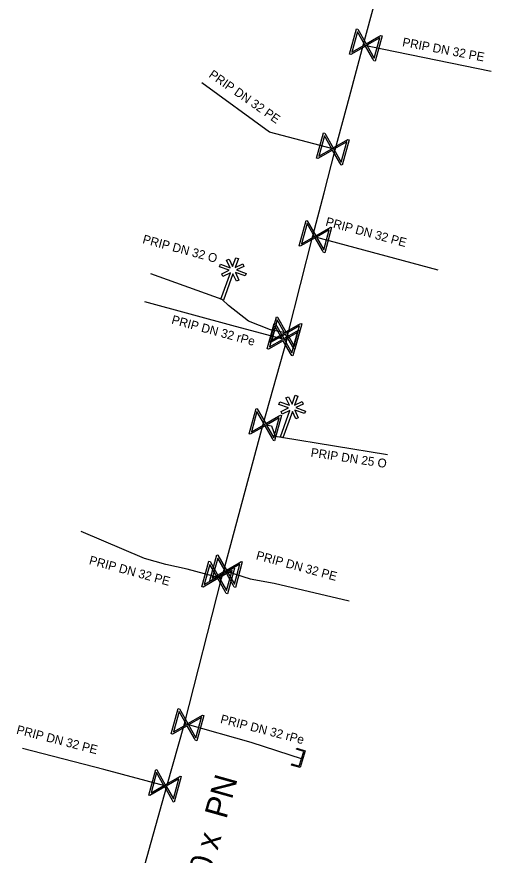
# Model space of a CAD drawing. Extents: x -643842 to -636370, y -1119190 to -1110210.
# Drawn here: x -641874.61 to -641847.68, y -1114927.07 to -1114879.49 of the extents above; entities that cross this region are included whole.
import ezdxf

# ---------------------------------------------------------------- set-up
doc = ezdxf.new("R2010")
doc.units = 0
for name, color, linetype in [('2', 7, 'Continuous'), ('22', 7, 'Continuous'), ('Level 16', 7, 'Continuous'), ('Level 20', 7, 'Continuous'), ('Level 21', 7, 'Continuous'), ('Level 23', 7, 'Continuous'), ('Level 4', 7, 'Continuous')]:
    doc.layers.add(name, color=color, linetype=linetype)

msp = doc.modelspace()

# ---------------------------------------------------------------- linework, layer by layer
at = {"layer": '2'}
for points in [[(-641862.359, -1114893.669), (-641862.177, -1114893.161), (-641862.03, -1114893.214), (-641862.21, -1114893.717), (-641861.787, -1114893.517), (-641861.721, -1114893.658), (-641862.141, -1114893.858), (-641861.599, -1114894.052), (-641861.652, -1114894.199), (-641862.203, -1114894.001), (-641862, -1114894.43), (-641862.141, -1114894.496), (-641862.339, -1114894.077), (-641862.874, -1114895.567), (-641863.021, -1114895.514), (-641862.485, -1114894.02), (-641862.912, -1114894.222), (-641862.977, -1114894.08), (-641862.549, -1114893.877), (-641863.1, -1114893.68), (-641863.047, -1114893.533), (-641862.506, -1114893.727), (-641862.703, -1114893.307), (-641862.562, -1114893.241), (-641862.359, -1114893.669)], [(-641858.989, -1114901.479), (-641858.807, -1114900.971), (-641858.66, -1114901.024), (-641858.84, -1114901.527), (-641858.417, -1114901.327), (-641858.351, -1114901.468), (-641858.771, -1114901.668), (-641858.229, -1114901.862), (-641858.282, -1114902.009), (-641858.833, -1114901.811), (-641858.63, -1114902.24), (-641858.771, -1114902.306), (-641858.969, -1114901.887), (-641859.504, -1114903.377), (-641859.651, -1114903.324), (-641859.115, -1114901.83), (-641859.542, -1114902.032), (-641859.607, -1114901.89), (-641859.179, -1114901.687), (-641859.73, -1114901.49), (-641859.677, -1114901.343), (-641859.136, -1114901.537), (-641859.333, -1114901.117), (-641859.192, -1114901.051), (-641858.989, -1114901.479)]]:
    msp.add_lwpolyline(points, dxfattribs=at)
at = {"layer": 'Level 16'}
for points in [[(-641853.878, -1114880.565), (-641854.274, -1114882.011), (-641854.337, -1114881.994), (-641854.397, -1114881.88), (-641854.814, -1114881.151), (-641855.657, -1114881.633), (-641855.72, -1114881.615), (-641855.324, -1114880.169), (-641855.261, -1114880.186), (-641854.781, -1114881.031), (-641854.052, -1114880.614), (-641853.941, -1114880.547), (-641853.878, -1114880.565)], [(-641855.59, -1114881.493), (-641854.858, -1114881.075), (-641855.275, -1114880.344), (-641855.59, -1114881.493)], [(-641854.01, -1114880.692), (-641854.738, -1114881.108), (-641854.322, -1114881.834), (-641854.01, -1114880.692)], [(-641855.749, -1114886.465), (-641856.145, -1114887.911), (-641856.208, -1114887.894), (-641856.268, -1114887.78), (-641856.685, -1114887.051), (-641857.528, -1114887.533), (-641857.591, -1114887.515), (-641857.195, -1114886.069), (-641857.132, -1114886.086), (-641856.652, -1114886.931), (-641855.923, -1114886.514), (-641855.812, -1114886.447), (-641855.749, -1114886.465)], [(-641857.461, -1114887.393), (-641856.729, -1114886.975), (-641857.146, -1114886.244), (-641857.461, -1114887.393)], [(-641855.881, -1114886.592), (-641856.609, -1114887.008), (-641856.193, -1114887.734), (-641855.881, -1114886.592)], [(-641856.739, -1114891.445), (-641857.135, -1114892.891), (-641857.198, -1114892.874), (-641857.258, -1114892.76), (-641857.675, -1114892.031), (-641858.518, -1114892.513), (-641858.581, -1114892.495), (-641858.185, -1114891.049), (-641858.122, -1114891.066), (-641857.642, -1114891.911), (-641856.913, -1114891.494), (-641856.802, -1114891.427), (-641856.739, -1114891.445)], [(-641858.451, -1114892.373), (-641857.719, -1114891.955), (-641858.136, -1114891.224), (-641858.451, -1114892.373)], [(-641856.871, -1114891.572), (-641857.599, -1114891.988), (-641857.183, -1114892.714), (-641856.871, -1114891.572)], [(-641858.429, -1114896.905), (-641858.825, -1114898.351), (-641858.888, -1114898.334), (-641858.948, -1114898.22), (-641859.365, -1114897.491), (-641860.208, -1114897.973), (-641860.271, -1114897.955), (-641859.875, -1114896.509), (-641859.812, -1114896.526), (-641859.332, -1114897.371), (-641858.603, -1114896.954), (-641858.492, -1114896.887), (-641858.429, -1114896.905)], [(-641860.141, -1114897.833), (-641859.409, -1114897.415), (-641859.826, -1114896.684), (-641860.141, -1114897.833)], [(-641858.549, -1114897.285), (-641858.945, -1114898.731), (-641859.008, -1114898.714), (-641859.068, -1114898.6), (-641859.485, -1114897.871), (-641860.328, -1114898.353), (-641860.391, -1114898.335), (-641859.995, -1114896.889), (-641859.932, -1114896.906), (-641859.452, -1114897.751), (-641858.723, -1114897.334), (-641858.612, -1114897.267), (-641858.549, -1114897.285)], [(-641860.261, -1114898.213), (-641859.529, -1114897.795), (-641859.946, -1114897.064), (-641860.261, -1114898.213)], [(-641858.561, -1114897.032), (-641859.289, -1114897.448), (-641858.873, -1114898.174), (-641858.561, -1114897.032)], [(-641858.681, -1114897.412), (-641859.409, -1114897.828), (-641858.993, -1114898.554), (-641858.681, -1114897.412)], [(-641859.579, -1114902.112), (-641859.975, -1114903.558), (-641860.039, -1114903.541), (-641860.099, -1114903.427), (-641860.516, -1114902.698), (-641861.358, -1114903.18), (-641861.422, -1114903.162), (-641861.026, -1114901.716), (-641860.962, -1114901.733), (-641860.483, -1114902.578), (-641859.754, -1114902.161), (-641859.643, -1114902.094), (-641859.579, -1114902.112)], [(-641861.291, -1114903.04), (-641860.559, -1114902.622), (-641860.977, -1114901.891), (-641861.291, -1114903.04)], [(-641859.711, -1114902.239), (-641860.439, -1114902.655), (-641860.024, -1114903.381), (-641859.711, -1114902.239)], [(-641861.809, -1114910.425), (-641862.205, -1114911.871), (-641862.268, -1114911.854), (-641862.328, -1114911.74), (-641862.745, -1114911.011), (-641863.588, -1114911.493), (-641863.651, -1114911.475), (-641863.255, -1114910.029), (-641863.192, -1114910.046), (-641862.712, -1114910.891), (-641861.983, -1114910.474), (-641861.872, -1114910.407), (-641861.809, -1114910.425)], [(-641862.259, -1114910.785), (-641862.655, -1114912.231), (-641862.718, -1114912.214), (-641862.778, -1114912.1), (-641863.195, -1114911.371), (-641864.038, -1114911.853), (-641864.101, -1114911.835), (-641863.705, -1114910.389), (-641863.642, -1114910.406), (-641863.162, -1114911.251), (-641862.433, -1114910.834), (-641862.322, -1114910.767), (-641862.259, -1114910.785)], [(-641863.971, -1114911.713), (-641863.239, -1114911.295), (-641863.656, -1114910.564), (-641863.971, -1114911.713)], [(-641863.521, -1114911.353), (-641862.789, -1114910.935), (-641863.206, -1114910.204), (-641863.521, -1114911.353)], [(-641861.941, -1114910.552), (-641862.669, -1114910.968), (-641862.253, -1114911.694), (-641861.941, -1114910.552)], [(-641862.391, -1114910.912), (-641863.119, -1114911.328), (-641862.703, -1114912.054), (-641862.391, -1114910.912)], [(-641863.999, -1114919.135), (-641864.395, -1114920.581), (-641864.458, -1114920.564), (-641864.518, -1114920.45), (-641864.935, -1114919.721), (-641865.778, -1114920.203), (-641865.841, -1114920.185), (-641865.445, -1114918.739), (-641865.382, -1114918.756), (-641864.902, -1114919.601), (-641864.173, -1114919.184), (-641864.062, -1114919.117), (-641863.999, -1114919.135)], [(-641865.711, -1114920.063), (-641864.979, -1114919.645), (-641865.396, -1114918.914), (-641865.711, -1114920.063)], [(-641864.131, -1114919.262), (-641864.859, -1114919.678), (-641864.443, -1114920.404), (-641864.131, -1114919.262)], [(-641865.279, -1114922.605), (-641865.675, -1114924.051), (-641865.738, -1114924.034), (-641865.798, -1114923.92), (-641866.215, -1114923.191), (-641867.058, -1114923.673), (-641867.121, -1114923.655), (-641866.725, -1114922.209), (-641866.662, -1114922.226), (-641866.182, -1114923.071), (-641865.453, -1114922.654), (-641865.342, -1114922.587), (-641865.279, -1114922.605)], [(-641866.991, -1114923.533), (-641866.259, -1114923.115), (-641866.676, -1114922.384), (-641866.991, -1114923.533)], [(-641865.411, -1114922.732), (-641866.139, -1114923.148), (-641865.723, -1114923.874), (-641865.411, -1114922.732)]]:
    msp.add_lwpolyline(points, dxfattribs=at)
at = {"layer": 'Level 21'}
msp.add_lwpolyline([(-641873.47, -1114940.04), (-641873.36, -1114939.63), (-641871.96, -1114938.85), (-641870.97, -1114937.91), (-641869.71, -1114934.99), (-641868.86, -1114933.02), (-641866.09, -1114923.16), (-641865.09, -1114919.61), (-641862.99, -1114911.36), (-641862.866, -1114910.908), (-641860.63, -1114902.61), (-641859.29, -1114897.85), (-641859.2, -1114897.44), (-641857.799, -1114891.927), (-641857.17, -1114889.48), (-641856.54, -1114887.03), (-641855.735, -1114884.04), (-641854.93, -1114881.05), (-641853.595, -1114876.09)], dxfattribs=at)
at = {"layer": 'Level 23'}
for points in [[(-641854.93, -1114881.05), (-641854.799, -1114881.09), (-641854.6, -1114881.157), (-641847.681, -1114882.573)], [(-641856.54, -1114887.03), (-641856.67, -1114886.99), (-641860.26, -1114886.04), (-641864.116, -1114883.242)], [(-641857.799, -1114891.927), (-641857.66, -1114891.97), (-641857.39, -1114892.05), (-641850.72, -1114893.84)], [(-641862.95, -1114895.54), (-641867.005, -1114894.085)], [(-641859.29, -1114897.85), (-641862.19, -1114897.07), (-641867.34, -1114895.67)], [(-641859.2, -1114897.44), (-641859.35, -1114897.43), (-641860.21, -1114897.25), (-641861.46, -1114896.76), (-641862.59, -1114895.87), (-641862.95, -1114895.54)], [(-641860.63, -1114902.61), (-641860.371, -1114902.664), (-641860.15, -1114902.71), (-641859.94, -1114903.28), (-641859.58, -1114903.35)], [(-641859.58, -1114903.35), (-641853.565, -1114904.327)], [(-641862.99, -1114911.36), (-641863.18, -1114911.31), (-641864.94, -1114910.84), (-641866.15, -1114910.57), (-641867.36, -1114910.23), (-641870.956, -1114908.691)], [(-641862.87, -1114910.91), (-641862.73, -1114910.95), (-641861.37, -1114911.39), (-641860, -1114911.64), (-641855.745, -1114912.636)], [(-641858.386, -1114921.62), (-641861.31, -1114920.68), (-641864.92, -1114919.66), (-641865.09, -1114919.61)], [(-641866.09, -1114923.16), (-641866.2, -1114923.13), (-641869.67, -1114922.21), (-641874.296, -1114921.015)]]:
    msp.add_lwpolyline(points, dxfattribs=at)
at = {"layer": 'Level 4'}
msp.add_lwpolyline([(-641858.992, -1114921.892), (-641858.574, -1114922.02), (-641858.318, -1114921.183), (-641858.736, -1114921.055), (-641858.718, -1114920.996), (-641858.24, -1114921.142), (-641858.532, -1114922.098), (-641859.01, -1114921.952), (-641858.992, -1114921.892)], dxfattribs=at)

# ---------------------------------------------------------------- texts
at = {"layer": '22'}
for s, rotation, p in [('PRIP DN 32 PE', 349.3283, (-641852.755, -1114881.153)), ('PRIP DN 32 PE', 325.085, (-641863.753, -1114882.875)), ('PRIP DN 32 PE', 344.9088, (-641857.119, -1114891.331)), ('PRIP DN 32 O', 344.9647, (-641867.506, -1114892.327)), ('PRIP DN 32 rPe', 344.792, (-641865.864, -1114896.893)), ('PRIP DN 25 O', 351.4194, (-641857.951, -1114904.449)), ('PRIP DN 32 PE', 344.7753, (-641870.543, -1114910.544)), ('PRIP DN 32 PE', 344.8188, (-641861.065, -1114910.269)), ('PRIP DN 32 rPe', 345.511, (-641863.09, -1114919.557)), ('PRIP DN 32 PE', 345.511, (-641874.665, -1114920.162))]:
    msp.add_text(s, height=0.5, rotation=rotation, dxfattribs=at).set_placement(p)
at = {"layer": 'Level 20'}
msp.add_text('TLT 100 x  PN ', height=1.3, rotation=74.3082, dxfattribs=at).set_placement((-641865.097, -1114933.524))

doc.saveas('drawing.dxf')
